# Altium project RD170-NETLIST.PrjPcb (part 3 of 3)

## Sheet 3.SchDoc
size 420 x 297 mm
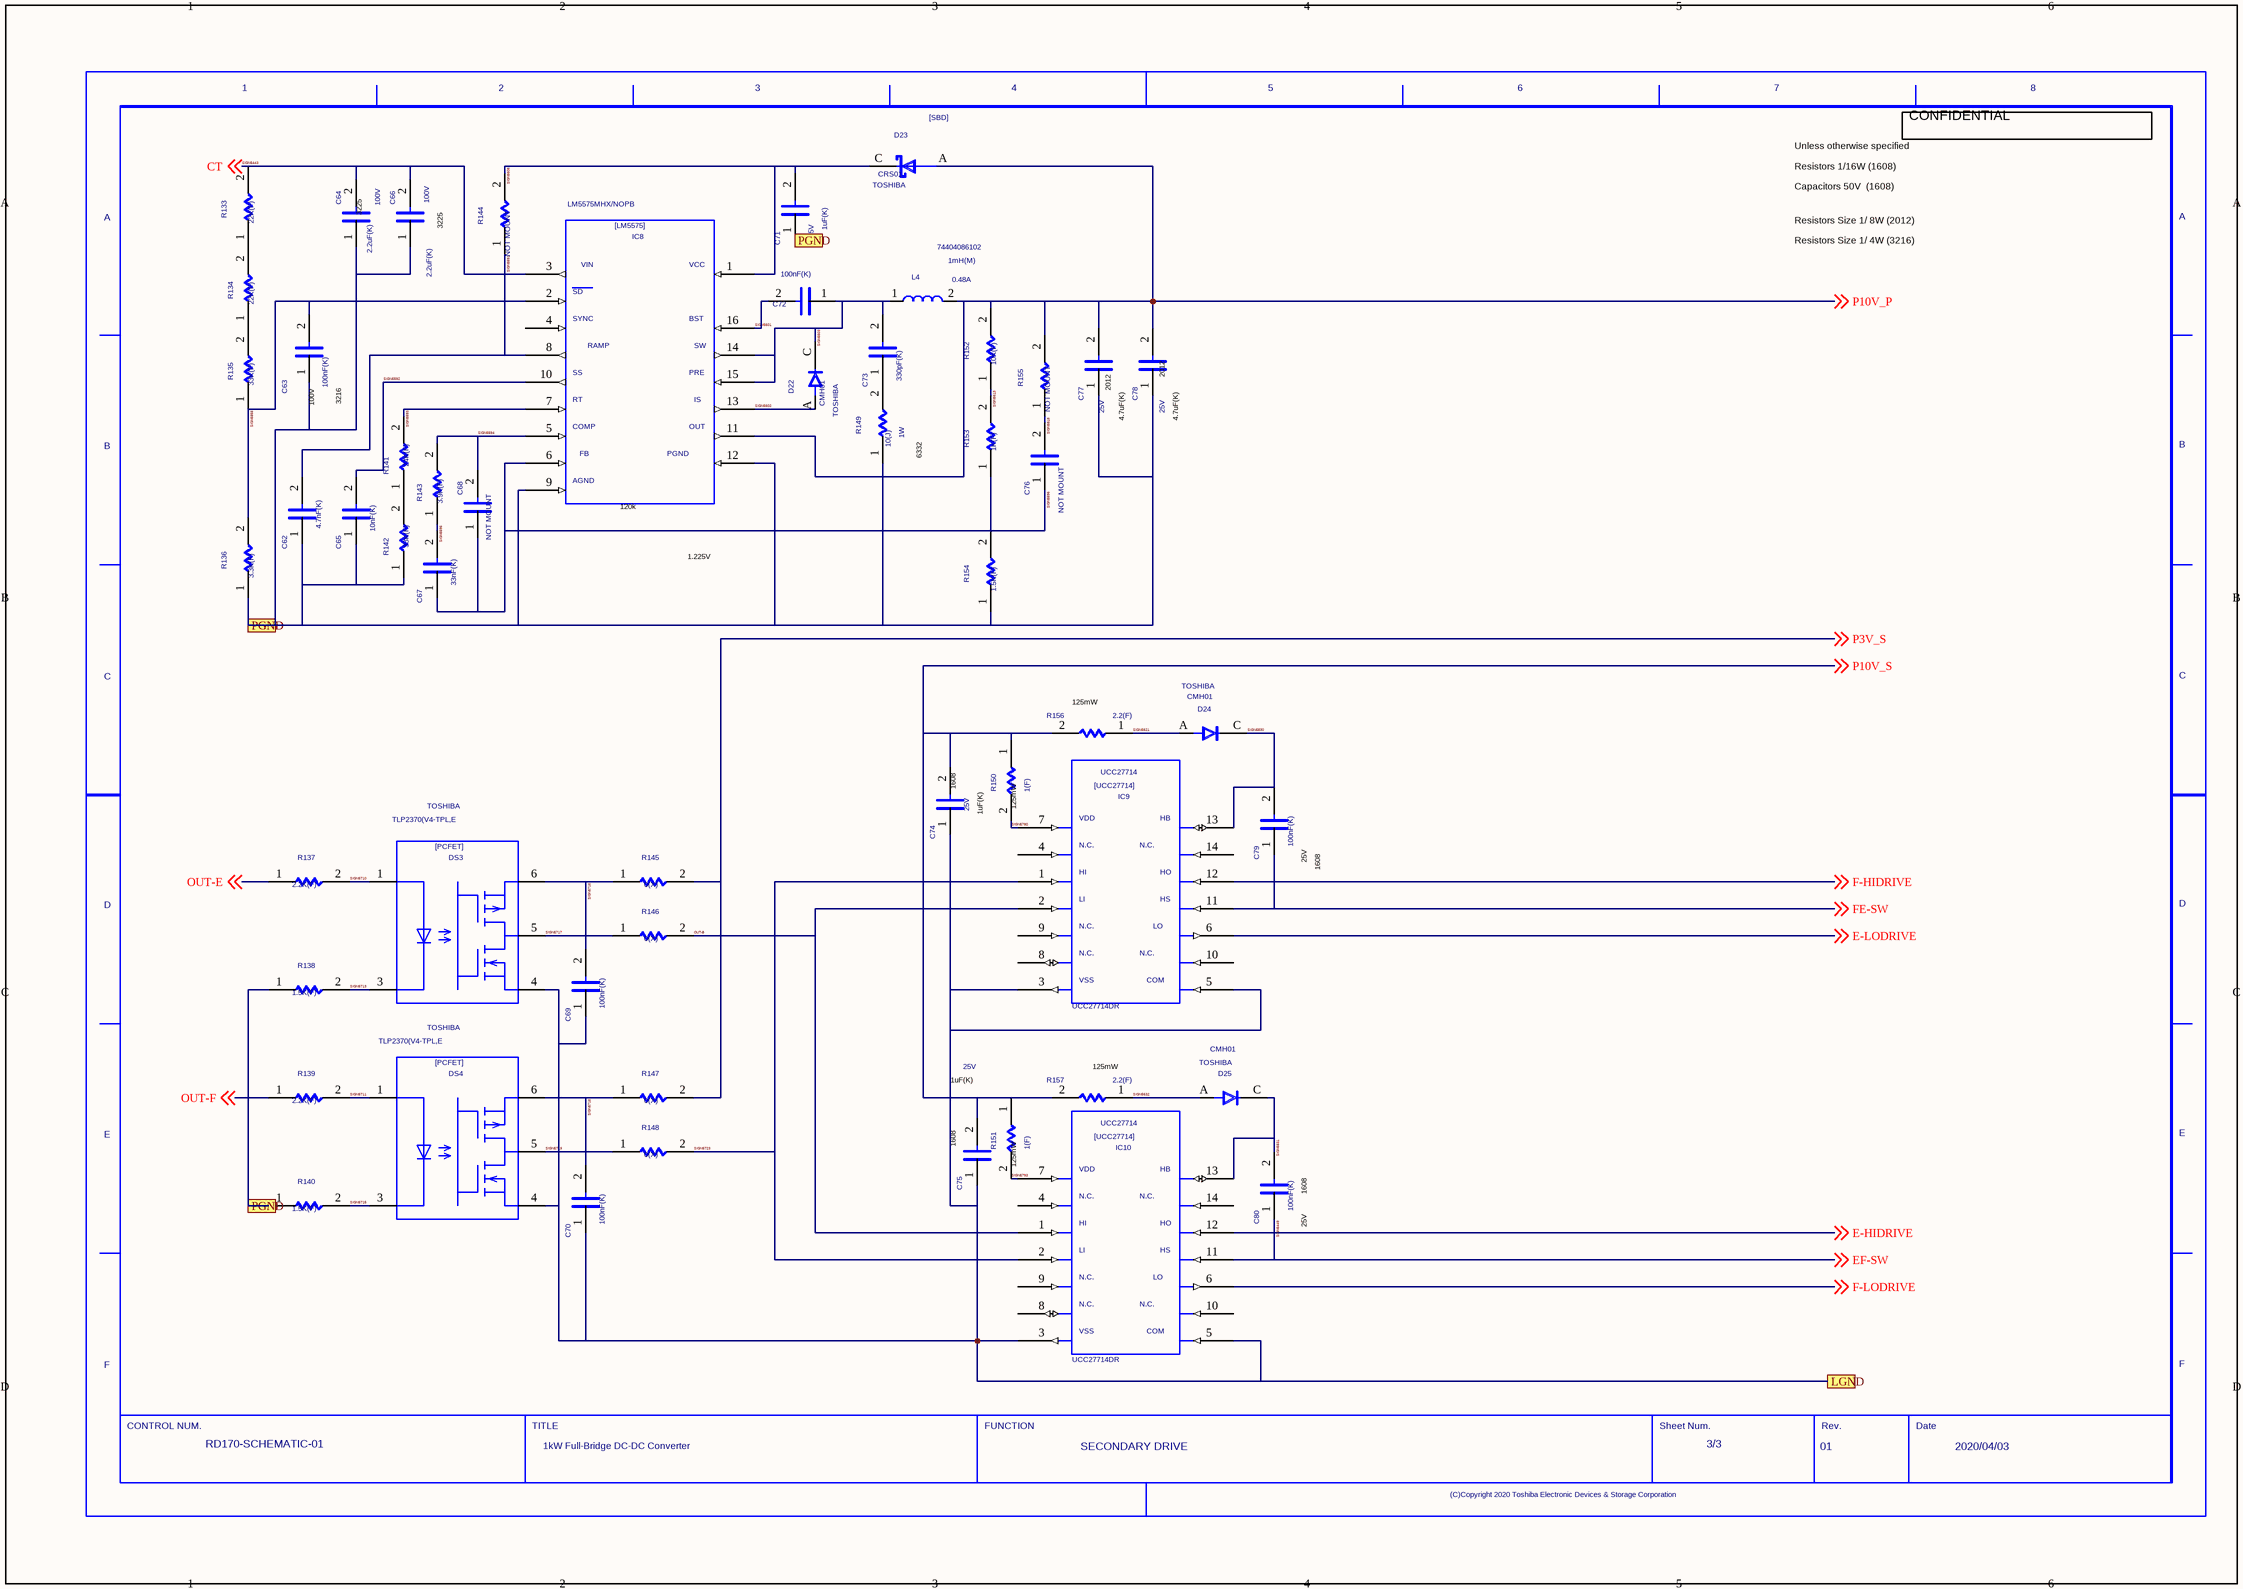
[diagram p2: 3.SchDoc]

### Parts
(Parts that share a designator on the sheet are numbered #1, #2 ... from top to bottom, then left to right.)
C62  VAL1: 4.7nF(K)  (hidden comment: C)
C63  VAL1: 100nF(K)  (hidden comment: C)
C64  VAL2: 100V  VAL1: 2.2uF(K)  (hidden comment: C)
C65  VAL1: 10nF(K)  (hidden comment: C)
C66  VAL2: 100V  VAL1: 2.2uF(K)  (hidden comment: C)
C67  VAL1: 33nF(K)  (hidden comment: C)
C68  NOTMOUNT: NOT MOUNT  (hidden comment: C)
C69  VAL1: 100nF(K)  (hidden comment: C)
C70  VAL1: 100nF(K)  (hidden comment: C)
C71  VAL2: 25V  VAL1: 1uF(K)  (hidden comment: C)
C72  VAL1: 100nF(K)  (hidden comment: C)
C73  VAL1: 330pF(K)  (hidden comment: C)
C74  VAL2: 25V  (hidden comment: C)
C75  VAL2: 25V  (hidden comment: C)
C76  NOTMOUNT: NOT MOUNT  (hidden comment: C)
C77  VAL2: 25V  (hidden comment: C)
C78  VAL2: 25V  (hidden comment: C)
C79  VAL1: 100nF(K)  (hidden comment: C)
C80  VAL1: 100nF(K)  (hidden comment: C)
D22  USERCOMPTEXT3: TOSHIBA  VAL3: CMH01  (hidden comment: D)
D23  USERCOMPTEXT3: TOSHIBA  VAL3: CRS01  (hidden comment: SBD)
D24  USERCOMPTEXT3: TOSHIBA  VAL3: CMH01  (hidden comment: D)
D25  USERCOMPTEXT3: TOSHIBA  VAL3: CMH01  (hidden comment: D)
DS3  USERCOMPTEXT3: TOSHIBA  VAL3: TLP2370(V4-TPL,E  (hidden comment: PCFET)
DS4  USERCOMPTEXT3: TOSHIBA  VAL3: TLP2370(V4-TPL,E  (hidden comment: PCFET)
IC8  VAL3: LM5575MHX/NOPB  (hidden comment: LM5575)
IC9  VAL3: UCC27714DR  (hidden comment: UCC27714)
IC10  VAL3: UCC27714DR  (hidden comment: UCC27714)
L4  VAL3: 74404086102  VAL2: 0.48A  VAL1: 1mH(M)  (hidden comment: L)
R133  VAL1: 22K(F)  (hidden comment: R)
R134  VAL1: 22K(F)  (hidden comment: R)
R135  VAL1: 33K(F)  (hidden comment: R)
R136  VAL1: 3.3K(F)  (hidden comment: R)
R137  VAL1: 2.2K(F)  (hidden comment: R)
R138  VAL1: 1.5K(F)  (hidden comment: R)
R139  VAL1: 2.2K(F)  (hidden comment: R)
R140  VAL1: 1.5K(F)  (hidden comment: R)
R141  VAL1: 24K(F)  (hidden comment: R)
R142  VAL1: 33K(F)  (hidden comment: R)
R143  VAL1: 3.9K(F)  (hidden comment: R)
R144  NOTMOUNT: NOT MOUNT  (hidden comment: R)
R145  VAL1: 0(X)  (hidden comment: R)
R146  VAL1: 0(X)  (hidden comment: R)
R147  VAL1: 0(X)  (hidden comment: R)
R148  VAL1: 0(X)  (hidden comment: R)
R149  VAL2: 1W  VAL1: 10(J)  (hidden comment: R)
R150  VAL1: 1(F)  (hidden comment: R)
R151  VAL1: 1(F)  (hidden comment: R)
R152  VAL1: 10K(F)  (hidden comment: R)
R153  VAL1: 1K(F)  (hidden comment: R)
R154  VAL1: 1.5K(F)  (hidden comment: R)
R155  NOTMOUNT: NOT MOUNT  (hidden comment: R)
R156  VAL1: 2.2(F)  (hidden comment: R)
R157  VAL1: 2.2(F)  (hidden comment: R)
U?#3  DATE: 2020/04/03  TITLE: 1kW Full-Bridge DC-DC Converter  DRAWINGNUMBER: RD170-SCHEMATIC-01  REVISION: 01  SHEETNUMBER: 3/3  FUNCTION: SECONDARY DRIVE  (hidden comment: WAKU_DEF100)

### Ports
LGND, PGND

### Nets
E-HIDRIVE: IC10.12 ; off-sheet E-HIDRIVE
E-LODRIVE: IC9.6 ; off-sheet E-LODRIVE
F-HIDRIVE: IC9.12 ; off-sheet F-HIDRIVE
F-LODRIVE: IC10.6 ; off-sheet F-LODRIVE
FE-SW: C79.1 IC9.11 ; off-sheet FE-SW
OUT-B: IC9.2 IC10.1 R146.2
OUT-E: R137.1 ; off-sheet OUT-E
OUT-F: R139.1 ; off-sheet OUT-F
P3V_S: R145.2 R147.2 ; off-sheet P3V_S
P10V_P: C77.2 C78.2 D23.A IC8.11 L4.2 R152.2 R155.2 ; off-sheet P10V_P
P10V_S: C74.2 C75.2 R150.1 R151.1 R156.2 R157.2 ; off-sheet P10V_S
PGND: C62.1 C63.1 C64.1 C65.1 C66.1 C71.1 C77.1 C78.1 IC8.9 IC8.12 R136.1 R138.1 R140.1 R142.1 R149.1 R154.1 ; port PGND
SIGN5443: C64.2 C66.2 IC8.3 R133.2 ; off-sheet CT  [also labelled CT]
SIGN5449: C80.1 IC10.11 ; off-sheet EF-SW  [also labelled EF-SW]
SIGN5591: C62.2 IC8.8 R144.1
SIGN5592: C65.2 IC8.10
SIGN5593: IC8.7 R141.2
SIGN5594: C68.2 IC8.5 R143.2
SIGN5595: C67.2 R143.1
SIGN5596: C67.1 C68.1 C76.1 IC8.6 R153.1 R154.2
SIGN5601: C72.2 IC8.16
SIGN5602: D22.A IC8.13
SIGN5603: C72.1 C73.2 D22.C IC8.14 IC8.15 L4.1
SIGN5608: C71.2 D23.C IC8.1 R144.2
SIGN5613: R152.1 R153.2
SIGN5621: D24.A R156.1
SIGN5632: D25.A R157.1
SIGN5710: DS3.1 R137.2
SIGN5711: DS4.1 R139.2
SIGN5713: DS3.3 R138.2
SIGN5715: DS4.3 R140.2
SIGN5716: C69.2 DS3.6 R145.1
SIGN5717: DS3.5 R146.1
SIGN5718: C70.2 DS4.6 R147.1
SIGN5719: DS4.5 R148.1
SIGN5723: IC9.1 IC10.2 R148.2
SIGN5780: IC9.7 R150.2
SIGN5793: IC10.7 R151.2
SIGN5818: C76.2 R155.1
SIGN5830: C79.2 D24.C IC9.13
SIGN5831: C80.2 D25.C IC10.13
SIGN5858: C63.2 IC8.2 R135.1 R136.2
SIGN5873: C69.1 C70.1 C74.1 C75.1 DS3.4 DS4.4 IC9.3 IC9.5 IC10.3 IC10.5 ; port LGND
NetC73_1: C73.1 R149.2
NetR133_1: R133.1 R134.2
NetR134_1: R134.1 R135.2
NetR141_1: R141.1 R142.2

Not connected (* = marked no-connect by the designer): IC8 4; IC9 4 8 9 10 14; IC10 4 8 9 10 14

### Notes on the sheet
- CONFIDENTIAL
- Resistors 1/16W (1608)
- Capacitors 50V  (1608)
- Unless otherwise specified
- (near C64) 3225
- (near C66) 3225
- Resistors Size 1/ 8W (2012)
- Resistors Size 1/ 4W (3216)
- (near C77) 2012
- (near C78) 2012
- (near C63) 100V
- (near C63) 3216
- (near R149) 6332
- 4.7uF(K)
- (near C78) 4.7uF(K)
- (near IC8) 120k
- 1.225V
  +-1.47%
- (near R156) 125mW
- (near C74) 1608
- 1uF(K)
- (near R150) 125mW
- (near C79) 25V
- (near C79) 1608
- (near R157) 125mW
- (near C75) 1608
- (near R151) 125mW
- (near C80) 1608
- (near C80) 25V

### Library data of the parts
C62 = C: SQ_PART_MODEL: CON_4.7n; FNPARTSNAMEG: CHIP CERAMIC CAPACITOR (1608); USEINPARTSLIST: YES; PARTNAME: G36030011280; OriginalSymbolOrigin: (2540,7620); ASIMVALUE: 4.7N; MFSOLDERINGPROP: .; TEMPCHARACTERI2: B; MFPACKAGEMETHOP: S; MFFORMINGDIVP: KC; OUMECLASSIFICATION: セラミックコンデンサ; SIZECODESMD: 1608; MFMOUNTSYMBOLP: 80; CDMASTERCADCELG: C8100E; PCODE: P03039090226; FNCLASSCODEG: P03-03; TOLERANCE: K; RATEDVOLTAGE: 50; COMPONENTNAME: G36030011280_package; MAXGCOUNT: 1; OUMEMAKER: MRT 村田製作所; OUMEMAKERKATAMEI: GRM39B472K50PT; VAL2: 50V
C63 = C: SQ_PART_MODEL: CON_100n; FNPARTSNAMEG: CHIP CERAMIC CAPACITOR (3216); USEINPARTSLIST: YES; PARTNAME: G36030031295; OriginalSymbolOrigin: (2540,7620); MFSOLDERINGPROP: .; TEMPCHARACTERI2: B; MFFORMINGDIVP: KC; OUMECLASSIFICATION: セラミックコンデンサ; SIZECODESMD: 3216; ASIMVALUE: 100N; MFMOUNTSYMBOLP: 90; CDMASTERCADCELG: DC901A; PCODE: P03042943816; FNCLASSCODEG: P03-03; MFPACKAGEMETHOP: S; TOLERANCE: K; RATEDVOLTAGE: 50; COMPONENTNAME: G36030031295_package; MAXGCOUNT: 1; OUMEMAKER: TYD 太陽誘電; OUMEMAKERKATAMEI: UMK316BJ104KD-T; VAL2: 100V
C64 C66 = C: SQ_PART_MODEL: CON_1u; FNPARTSNAMEG: CHIP CERAMIC CAPACITOR (3216); USEINPARTSLIST: YES; PARTNAME: G36030013017; OriginalSymbolOrigin: (2540,7620); MFSOLDERINGPROP: .; TEMPCHARACTERI2: B; MFPACKAGEMETHOP: S; MFFORMINGDIVP: KC; OUMECLASSIFICATION: セラミックコンデンサ; SIZECODESMD: 3216; MFMOUNTSYMBOLP: 90; CDMASTERCADCELG: DC901A; PCODE: P03042992821; FNCLASSCODEG: P03-03; TOLERANCE: K; RATEDVOLTAGE: 50; COMPONENTNAME: 5P9L1192P006_package; MAXGCOUNT: 1; OUMEMAKER: 株式会社村田製作所; NOMINALCAPACITA: 1u; OUMEMAKERKATAMEI: GRM31MB31H105KA87L; VAL3: 8.85E+11
C65 = C: SQ_PART_MODEL: CON_10n; FNPARTSNAMEG: CHIP CERAMIC CAPACITOR (1608); USEINPARTSLIST: YES; PARTNAME: G36030011716; OriginalSymbolOrigin: (2540,7620); ASIMVALUE: 10N; MFSOLDERINGPROP: .; TEMPCHARACTERI2: B; MFPACKAGEMETHOP: S; MFFORMINGDIVP: KC; OUMECLASSIFICATION: セラミックコンデンサ; SIZECODESMD: 1608; MFMOUNTSYMBOLP: 80; CDMASTERCADCELG: C8100E; PCODE: P03039A11122; FNCLASSCODEG: P03-03; TOLERANCE: K; RATEDVOLTAGE: 50; COMPONENTNAME: G36030011075_package; MAXGCOUNT: 1; OUMEMAKER: KYC 京セラ; FUNCTION: G36030011075; OUMEMAKERKATAMEI: CM105W5R103K50AT; VAL2: 50V
C67 = C: SQ_PART_MODEL: CON_33n; FNPARTSNAMEG: CHIP CERAMIC CAPACITOR (1608); USEINPARTSLIST: YES; PARTNAME: G36030011310; OriginalSymbolOrigin: (2540,7620); MFSOLDERINGPROP: .; TEMPCHARACTERI2: B; MFPACKAGEMETHOP: S; MFFORMINGDIVP: KC; OUMECLASSIFICATION: セラミックコンデンサ; SIZECODESMD: 1608; MFMOUNTSYMBOLP: 80; CDMASTERCADCELG: C8100E; PCODE: P03039AB8428; FNCLASSCODEG: P03-03; RATEDVOLTAGE: 50; COMPONENTNAME: G510310AM108_package; MAXGCOUNT: 1; OUMEMAKER: ROH ロー・; NOMINALCAPACITA: 33n; OUMEMAKERKATAMEI: MCH185C333KK; VAL2: 50V; CAPACITANCETOLE: K
C68 = C: FNPARTSNAMEG: CHIP CERAMIC CAPACITOR (1608); USEINPARTSLIST: YES; PARTNAME: G36030011488; OriginalSymbolOrigin: (2540,7620); TEMPCHARACTERI2: CH; MFMOUNTSYMBOLP: 80; CDMASTERCADCELG: C8100E; MFSOLDERINGPROP: .; MFPACKAGEMETHOP: S; MFFORMINGDIVP: KC; OUMECLASSIFICATION: セラミックコンデンサ; SIZECODESMD: 1608; PCODE: P03039269127; FNCLASSCODEG: P03-03; RATEDVOLTAGE: 50; COMPONENTNAME: G36030011488_package; MAXGCOUNT: 1; OUMEMAKER: KYC 京セラ; NOMINALCAPACITA: 220p; OUMEMAKERKATAMEI: CM105CH221J50AT; CAPACITANCETOLE: J
C69 C70 = C: SQ_PART_MODEL: CON_100n; FNPARTSNAMEG: CHIP CERAMIC CAPACITOR (1608); PARTCOMMENT: 代表セル<KC0008> がフットプリントに登録されていません。; USEINPARTSLIST: YES; PARTNAME: G36030011839; OriginalSymbolOrigin: (2540,7620); MFSOLDERINGPROP: .; TEMPCHARACTERI2: B; MFFORMINGDIVP: KC; OUMECLASSIFICATION: セラミックコンデンサ; SIZECODESMD: 1608; MFMOUNTSYMBOLP: 80; CDMASTERCADCELG: KC0008; PCODE: P03B000001KW; FNCLASSCODEG: P03-03; MFPACKAGEMETHOP: S; RATEDVOLTAGE: 50; COMPONENTNAME: GDM030001005_package; MAXGCOUNT: 1; OUMEMAKER: MRT 村田製作所; NOMINALCAPACITA: 100n; OUMEMAKERKATAMEI: GRM188B31H104KA92D; VAL2: 50V; CAPACITANCETOLE: K
C71 = C: SQ_PART_MODEL: CON_1u; FNPARTSNAMEG: CHIP CERAMIC CAPACITOR (1608); USEINPARTSLIST: YES; PARTNAME: GDM030000707; PARTCOMMENT: 代表セル<KC0008> がフットプリントに登録されていません。; OriginalSymbolOrigin: (2540,7620); MFSOLDERINGPROP: .; TEMPCHARACTERI2: B; MFPACKAGEMETHOP: S; MFFORMINGDIVP: KC; OUMECLASSIFICATION: セラミックコンデンサ; SIZECODESMD: 1608; MFMOUNTSYMBOLP: 80; CDMASTERCADCELG: KC0008; PCODE: P03B0000016L; FNCLASSCODEG: P03-03; RATEDVOLTAGE: 25; COMPONENTNAME: GDM030000346_package; MAXGCOUNT: 1; OUMEMAKER: KYC 京セラ; NOMINALCAPACITA: 1u; OUMEMAKERKATAMEI: CV105B105K25AT; CAPACITANCETOLE: K
C72 = C: SQ_PART_MODEL: CON_100n; FNPARTSNAMEG: CHIP CERAMIC CAPACITOR (1608); USEINPARTSLIST: YES; PARTNAME: G36030011297; PARTCOMMENT: 代表セル<KC0008> がフットプリントに登録されていません。; OriginalSymbolOrigin: (2540,7620); MAXGCOUNT: 1; COMPONENTNAME: GDM030001005_package; MFSOLDERINGPROP: .; TEMPCHARACTERI2: B; OUMEMAKER: MRT 村田製作所; MFPACKAGEMETHOP: S; MFFORMINGDIVP: KC; OUMECLASSIFICATION: セラミックコンデンサ; MFMOUNTSYMBOLP: 80; OUMEMAKERKATAMEI: GRM188B31H104KA92D; VAL2: 50V; CDMASTERCADCELG: KC0008; PCODE: P03B000001KW; FNCLASSCODEG: P03-03; SIZECODESMD: 1608; RATEDVOLTAGE: 50; NOMINALCAPACITA: 100n; CAPACITANCETOLE: K
C73 = C: SQ_PART_MODEL: CON_330p; FNPARTSNAMEG: CHIP CERAMIC CAPACITOR (1608); USEINPARTSLIST: YES; PARTNAME: GDM030000706; PARTCOMMENT: 代表セル<KC0008> がフットプリントに登録されていません。; OriginalSymbolOrigin: (2540,7620); OUMECLASSIFICATION: セラミックコンデンサ; SIZECODESMD: 1608; CDMASTERCADCELG: KC0008; FNCLASSCODEG: P03-03; RATEDVOLTAGE: 50; COMPONENTNAME: K0300251_package; MAXGCOUNT: 1; OUMEMAKER: ROH; NOMINALCAPACITA: 330p; OUMEMAKERKATAMEI: MCH185CN331KK; VAL2: 50V; CAPACITANCETOLE: K
C74 = C: SQ_PART_MODEL: CON_100n; FNPARTSNAMEG: CHIP CERAMIC CAPACITOR (1608); USEINPARTSLIST: YES; PARTNAME: G36030104036; OriginalSymbolOrigin: (2540,7620); MFSOLDERINGPROP: .; TEMPCHARACTERI2: B; MFPACKAGEMETHOP: S; MFFORMINGDIVP: KC; OUMECLASSIFICATION: セラミックコンデンサ; SIZECODESMD: 1608; MFMOUNTSYMBOLP: 80; CDMASTERCADCELG: C8100E; PCODE: P03039A6F224; FNCLASSCODEG: P03-03; RATEDVOLTAGE: 25; COMPONENTNAME: G36030104036_package; MAXGCOUNT: 1; OUMEMAKER: MRT 村田製作所; NOMINALCAPACITA: 100n; OUMEMAKERKATAMEI: GRM39B104K25PT; VAL1: 1uF(K); CAPACITANCETOLE: K
C75 = C: SQ_PART_MODEL: CON_100n; FNPARTSNAMEG: CHIP CERAMIC CAPACITOR (1608); USEINPARTSLIST: YES; PARTNAME: G36030104036; OriginalSymbolOrigin: (2540,7620); PCODE: P03039A6F224; MFSOLDERINGPROP: .; TEMPCHARACTERI2: B; MFPACKAGEMETHOP: S; MFFORMINGDIVP: KC; OUMECLASSIFICATION: セラミックコンデンサ; SIZECODESMD: 1608; MFMOUNTSYMBOLP: 80; CDMASTERCADCELG: C8100E; FNCLASSCODEG: P03-03; RATEDVOLTAGE: 25; COMPONENTNAME: G36030104036_package; MAXGCOUNT: 1; OUMEMAKER: MRT 村田製作所; NOMINALCAPACITA: 100n; OUMEMAKERKATAMEI: GRM39B104K25PT; VAL1: 1uF(K); CAPACITANCETOLE: K
C76 = C: FNPARTSNAMEG: CHIP CERAMIC CAPACITOR (1608); USEINPARTSLIST: YES; PARTNAME: GDM030000714; PARTCOMMENT: 代表セル<KC0008> がフットプリントに登録されていません。; OriginalSymbolOrigin: (2540,7620); PCODE: P03B000001KW; MFSOLDERINGPROP: .; TEMPCHARACTERI2: B; MFPACKAGEMETHOP: S; MFFORMINGDIVP: KC; OUMECLASSIFICATION: セラミックコンデンサ; SIZECODESMD: 1608; MFMOUNTSYMBOLP: 80; CDMASTERCADCELG: KC0008; FNCLASSCODEG: P03-03; RATEDVOLTAGE: 50; COMPONENTNAME: GDM030001137_package; MAXGCOUNT: 1; OUMEMAKER: MRT 村田製作所; NOMINALCAPACITA: 100n; OUMEMAKERKATAMEI: GRM188B31H104KA92D; CAPACITANCETOLE: K
C77 = C: SQ_PART_MODEL: CON_470n; FNPARTSNAMEG: CHIP CERAMIC CAPACITOR (2012); USEINPARTSLIST: YES; PARTNAME: G36030029759; OriginalSymbolOrigin: (2540,7620); VAL3: 8.85E+11; PCODE: P03261001113; CDMASTERCADCELG: DC910A; MFMOUNTSYMBOLP: 90; MFSOLDERINGPROP: .; TEMPCHARACTERI2: B; MFPACKAGEMETHOP: S; MFFORMINGDIVP: KC; OUMECLASSIFICATION: セラミックコンデンサ; SIZECODESMD: 2012; FNCLASSCODEG: P03-03; RATEDVOLTAGE: 25; COMPONENTNAME: G36030029759_package; MAXGCOUNT: 1; OUMEMAKER: KYC 京セラ; NOMINALCAPACITA: 470n; OUMEMAKERKATAMEI: CM21B474K25AT; VAL1: 4.7uF(K); CAPACITANCETOLE: K
C78 = C: SQ_PART_MODEL: CON_470n; FNPARTSNAMEG: CHIP CERAMIC CAPACITOR (2012); USEINPARTSLIST: YES; PARTNAME: G36030029759; OriginalSymbolOrigin: (2540,7620); VAL3: 8.85E+11; PCODE: P03261001113; MFSOLDERINGPROP: .; TEMPCHARACTERI2: B; MFPACKAGEMETHOP: S; MFFORMINGDIVP: KC; OUMECLASSIFICATION: セラミックコンデンサ; SIZECODESMD: 2012; MFMOUNTSYMBOLP: 90; CDMASTERCADCELG: DC910A; FNCLASSCODEG: P03-03; RATEDVOLTAGE: 25; COMPONENTNAME: G36030029759_package; MAXGCOUNT: 1; OUMEMAKER: KYC 京セラ; NOMINALCAPACITA: 470n; OUMEMAKERKATAMEI: CM21B474K25AT; VAL1: 4.7uF(K); CAPACITANCETOLE: K
C79 = C: SQ_PART_MODEL: CON_100n; FNPARTSNAMEG: CHIP CERAMIC CAPACITOR (3216); USEINPARTSLIST: YES; PARTNAME: G36030104036; OriginalSymbolOrigin: (2540,7620); MFSOLDERINGPROP: .; TEMPCHARACTERI2: B; MFFORMINGDIVP: KC; OUMECLASSIFICATION: セラミックコンデンサ; SIZECODESMD: 3216; ASIMVALUE: 100N; MFMOUNTSYMBOLP: 90; CDMASTERCADCELG: DC901A; PCODE: P03042943816; FNCLASSCODEG: P03-03; MFPACKAGEMETHOP: S; TOLERANCE: K; RATEDVOLTAGE: 50; COMPONENTNAME: G36030031295_package; MAXGCOUNT: 1; OUMEMAKER: TYD 太陽誘電; OUMEMAKERKATAMEI: UMK316BJ104KD-T; VAL2: 25V
C80 = C: SQ_PART_MODEL: CON_100n; FNPARTSNAMEG: CHIP CERAMIC CAPACITOR (3216); USEINPARTSLIST: YES; PARTNAME: G36030104036; OriginalSymbolOrigin: (2540,7620); MFSOLDERINGPROP: .; TEMPCHARACTERI2: B; MFFORMINGDIVP: KC; OUMECLASSIFICATION: セラミックコンデンサ; SIZECODESMD: 3216; ASIMVALUE: 100N; MFMOUNTSYMBOLP: 90; CDMASTERCADCELG: DC901A; PCODE: P03042943816; FNCLASSCODEG: P03-03; MFPACKAGEMETHOP: S; TOLERANCE: K; RATEDVOLTAGE: 50; COMPONENTNAME: G36030031295_package; MAXGCOUNT: 1; OUMEMAKER: TYD 太陽誘電; OUMEMAKERKATAMEI: UMK316BJ104KD-T; VAL2: 50V
D22 D24 D25 = D: USEINPARTSLIST: YES; PARTNAME: 5P9L1110P002; SAVEAREA0: -565,-171,12979,8058; SAVECOUNT: 1; OriginalSymbolOrigin: (2540,5080); COMPONENTNAME: D_D; OUMEMAKER: 東芝; OUMEMAKERKATAMEI: CMF02(TE12R,Q); VAL1: CMH01(TE12L,Q)
D23 = SBD: FNPARTSNAMEG: SCHOTTKY BARRIER DIODE; USEINPARTSLIST: YES; PARTNAME: G36420146011; OUMEPARTTYPE: D; OriginalSymbolOrigin: (0,5080); FORWARDVOLTAGEM: 0; COMPONENTNAME: G36420146011_package; MAXGCOUNT: 1; MAXREPETITIVEPE: 30; MFSOLDERINGPROP: .; OUMEMAKER: TSB 東芝（ＹＰＳＳ）; QUADMODEL: dummymodel; MFPACKAGEMETHOP: S; PEAKFORWARDVOLT: 360m; MFFORMINGDIVP: MM; MOUNTINGFORMSMD: SMD; OUMECLASSIFICATION: 一般整流素子; MFMOUNTSYMBOLP: 80; OUMEMAKERKATAMEI: CRS01(TE85L); VAL1: CRS01(TE85L,Q); CDMASTERCADCELG: DD831R; PCODE: P42471001117; FNCLASSCODEG: P42-03
DS3 DS4 = PCFET: USEINPARTSLIST: YES; PARTNAME: TLP2370_V4-TPL_E; TIME: 11:37:10; UPDATEUSER: q91866sr; UPDATETIME: 16:31:08; SAVECOUNT: 14; SAVEAREA0: -7234,-371,40293,35914; OriginalSymbolOrigin: (5080,33020); MAXGCOUNT: 1; COMPONENTNAME: pinass:PCFET_func:PCFET; OUMEMAKER: 東芝
IC8 = LM5575: USEINPARTSLIST: YES; SAVECOUNT: 74; SAVEAREA0: -22463,-689,65805,66700; TIME: 14:20:25; UPDATEUSER: q91866sr; UPDATETIME: 16:21:18; OriginalSymbolOrigin: (7620,60960); COMPONENTNAME: pinass:LM5575_func:LM5575; MAXGCOUNT: 1; OUMEMAKER: TI
IC9 IC10 = UCC27714: PARTS: 1; SAVECOUNT: 17; SAVEAREA0: -9583,0,50301,45720; TIME: 14:04:55; UPDATEUSER: q91866sr; UPDATETIME: 15:13:25; DEVICENAME: 74HC244AF; DEVICE: 74VHC245; PKG_TYPE: 20PIN; LEVEL: STD; HETERO: 74VHC245,74VHC245_P; OriginalSymbolOrigin: (7620,45720); FUNCTION: IRS21864S
L4 = L: USEINPARTSLIST: YES; OriginalSymbolOrigin: (2540,5080); MAXGCOUNT: 1; COMPONENTNAME: pinass:L_func:L; OUMEMAKER: WURTH
R133 R134 = R: SQ_PART_MODEL: RES_22K; FNPARTSNAMEG: CHIP RESISTOR (1608); USEINPARTSLIST: YES; PARTNAME: G36010011064; OriginalSymbolOrigin: (5080,5080); TOLERANCE: F; ASIMVALUE: 22K; COMPONENTNAME: G36010027089_package; MAXGCOUNT: 1; MFSOLDERINGPROP: .; OUMEMAKER: KOA ＫＯＡ; MFPACKAGEMETHOP: S; MFFORMINGDIVP: KC; MOUNTINGFORMSMD: SMD; OUMECLASSIFICATION: 表面実装用固定抵抗器; MFMOUNTSYMBOLP: 80; POWERRATING: 63m; OUMEMAKERKATAMEI: RK73H1JTD2202F; NUMBEROFELEMENT: 0; VAL2: 63mW; CDMASTERCADCELG: DR802R; PCODE: P01042207426; FNCLASSCODEG: P01-08
R135 = R: SQ_PART_MODEL: RES_33K; FNPARTSNAMEG: CHIP RESISTOR (1608); USEINPARTSLIST: YES; PARTNAME: GDM010001114; OriginalSymbolOrigin: (5080,5080); TOLERANCE: F; ASIMVALUE: 33K; COMPONENTNAME: G36010027171_package; MAXGCOUNT: 1; MFSOLDERINGPROP: .; OUMEMAKER: NAE 松下電子部品; MFPACKAGEMETHOP: S; MFFORMINGDIVP: KC; MOUNTINGFORMSMD: SMD; OUMECLASSIFICATION: 表面実装用固定抵抗器; MFMOUNTSYMBOLP: 80; POWERRATING: 63m; OUMEMAKERKATAMEI: ERJ3GEYF333V; NUMBEROFELEMENT: 0; VAL2: 63mW; CDMASTERCADCELG: DR802R; PCODE: P01042295621; FNCLASSCODEG: P01-08
R136 = R: SQ_PART_MODEL: RES_3.3K; FNPARTSNAMEG: CHIP RESISTOR (1608); USEINPARTSLIST: YES; PARTNAME: GDM010001020; OriginalSymbolOrigin: (5080,5080); TOLERANCE: F; ASIMVALUE: 3.3K; COMPONENTNAME: G36010027027_package; MAXGCOUNT: 1; MFSOLDERINGPROP: .; OUMEMAKER: ROH ロー・; MFPACKAGEMETHOP: S; MFFORMINGDIVP: KC; MOUNTINGFORMSMD: SMD; OUMECLASSIFICATION: 表面実装用固定抵抗器; MFMOUNTSYMBOLP: 80; POWERRATING: 63m; OUMEMAKERKATAMEI: MCR03EZPFX3301; NUMBEROFELEMENT: 0; VAL2: 63mW; CDMASTERCADCELG: DR802R; PCODE: P01042250729; FNCLASSCODEG: P01-08
R137 R139 = R: SQ_PART_MODEL: RES_2.2K; FNPARTSNAMEG: CHIP RESISTOR (1608); USEINPARTSLIST: YES; PARTNAME: G36010104339; OriginalSymbolOrigin: (5080,5080); COMPONENTNAME: G36010104339_package; MAXGCOUNT: 1; MFSOLDERINGPROP: .; OUMEMAKER: KOA ＫＯＡ; MFPACKAGEMETHOP: S; MFFORMINGDIVP: KC; MOUNTINGFORMSMD: SMD; OUMECLASSIFICATION: 表面実装用固定抵抗器; RESISTANCETOLER: F; MFMOUNTSYMBOLP: 80; POWERRATING: 63m; OUMEMAKERKATAMEI: RK73H1JTD2201F; NOMINALRESISTAN: 2.2K; NUMBEROFELEMENT: 0; VAL2: 63mW; CDMASTERCADCELG: DR802R; PCODE: P01042159428; FNCLASSCODEG: P01-08
R138 R140 R154 = R: SQ_PART_MODEL: RES_1.5K; FNPARTSNAMEG: CHIP RESISTOR (1608); USEINPARTSLIST: YES; PARTNAME: G36010027232; OriginalSymbolOrigin: (5080,5080); TOLERANCE: F; COMPONENTNAME: G36010027232_package; MAXGCOUNT: 1; MFSOLDERINGPROP: .; OUMEMAKER: HDK 北陸電気工業; MFPACKAGEMETHOP: S; MFFORMINGDIVP: KC; MOUNTINGFORMSMD: SMD; OUMECLASSIFICATION: 表面実装用固定抵抗器; ASIMVALUE: 1.5K; MFMOUNTSYMBOLP: 80; POWERRATING: 63m; OUMEMAKERKATAMEI: CR1/16 152FV; NUMBEROFELEMENT: 0; VAL2: 63mW; CDMASTERCADCELG: DR802R; PCODE: P01042512223; FNCLASSCODEG: P01-08
R141 = R: SQ_PART_MODEL: RES_24K; FNPARTSNAMEG: CHIP RESISTOR (1608); USEINPARTSLIST: YES; PARTNAME: G36010027A34; OriginalSymbolOrigin: (5080,5080); TOLERANCE: F; COMPONENTNAME: G36010027A34_package; MAXGCOUNT: 1; MFSOLDERINGPROP: .; OUMEMAKER: KOA ＫＯＡ; MFPACKAGEMETHOP: S; MFFORMINGDIVP: KC; MOUNTINGFORMSMD: SMD; OUMECLASSIFICATION: 表面実装用固定抵抗器; ASIMVALUE: 24K; MFMOUNTSYMBOLP: 80; POWERRATING: 63m; OUMEMAKERKATAMEI: RK73H1JTD2402F; NUMBEROFELEMENT: 0; VAL2: 63mW; CDMASTERCADCELG: DR802R; PCODE: P01042223426; FNCLASSCODEG: P01-08
R142 = R: SQ_PART_MODEL: RES_33K; FNPARTSNAMEG: CHIP RESISTOR (1608); USEINPARTSLIST: YES; PARTNAME: G36010027171; OriginalSymbolOrigin: (5080,5080); TOLERANCE: F; COMPONENTNAME: G36010027171_package; MAXGCOUNT: 1; MFSOLDERINGPROP: .; OUMEMAKER: NAE 松下電子部品; MFPACKAGEMETHOP: S; MFFORMINGDIVP: KC; MOUNTINGFORMSMD: SMD; OUMECLASSIFICATION: 表面実装用固定抵抗器; ASIMVALUE: 33K; MFMOUNTSYMBOLP: 80; POWERRATING: 63m; OUMEMAKERKATAMEI: ERJ3GEYF333V; NUMBEROFELEMENT: 0; VAL2: 63mW; CDMASTERCADCELG: DR802R; PCODE: P01042295621; FNCLASSCODEG: P01-08
R143 = R: SQ_PART_MODEL: RES_3.9K; FNPARTSNAMEG: CHIP RESISTOR (1608); USEINPARTSLIST: YES; PARTNAME: G36010027102; OriginalSymbolOrigin: (5080,5080); TOLERANCE: F; COMPONENTNAME: G36010104254_package; MAXGCOUNT: 1; MFSOLDERINGPROP: .; OUMEMAKER: HDK 北陸電気工業; MFPACKAGEMETHOP: S; MFFORMINGDIVP: KC; MOUNTINGFORMSMD: SMD; OUMECLASSIFICATION: 表面実装用固定抵抗器; ASIMVALUE: 3.9K; MFMOUNTSYMBOLP: 80; POWERRATING: 63m; OUMEMAKERKATAMEI: CR1/16 392FV; NUMBEROFELEMENT: 0; VAL2: 63mW; CDMASTERCADCELG: DR802R; PCODE: P01042262227; FNCLASSCODEG: P01-08
R144 = R: FNPARTSNAMEG: CHIP RESISTOR (2012); USEINPARTSLIST: YES; PARTNAME: 5P9L1083P100; OriginalSymbolOrigin: (5080,5080); TOLERANCE: F; COMPONENTNAME: 5P9L1083P100_package; MAXGCOUNT: 1; MFSOLDERINGPROP: .; OUMEMAKER: 北陸電気工業; MFPACKAGEMETHOP: S; MFFORMINGDIVP: KC; MOUNTINGFORMSMD: SMD; OUMECLASSIFICATION: 表面実装用固定抵抗器; MFMOUNTSYMBOLP: 90; POWERRATING: 100m; OUMEMAKERKATAMEI: CR1/10 100FV Pb(F); NOMINALRESISTAN: 10; NUMBEROFELEMENT: 0; CDMASTERCADCELG: DR910A; PCODE: P01043091222; FNCLASSCODEG: P01-08
R145-R148 = R: SQ_PART_MODEL: RES_0; FNPARTSNAMEG: CHIP JUMPER 1608TYPE; USEINPARTSLIST: YES; PARTNAME: G36010014584; PARTCOMMENT: 代表セル<KC0008> がフットプリントに登録されていません。; OriginalSymbolOrigin: (5080,5080); COMPONENTNAME: K0100346_package; MAXGCOUNT: 1; OUMEMAKER: TAT; OUMECLASSIFICATION: 表面実装用固定抵抗器; RESISTANCETOLER: X; POWERRATING: 63m; OUMEMAKERKATAMEI: TSR3GR00V; NOMINALRESISTAN: 0; VAL2: 63mW; CDMASTERCADCELG: KC0008; FNCLASSCODEG: P01-08
R149 = R: SQ_PART_MODEL: RES_10; FNPARTSNAMEG: CHIP RESISTOR (6432); USEINPARTSLIST: YES; PARTNAME: 5P9L1082P003; OriginalSymbolOrigin: (5080,5080); MAXGCOUNT: 1; COMPONENTNAME: 5P9L1082P003_package; MFSOLDERINGPROP: .; OUMEMAKER: 北陸電気工業; MFPACKAGEMETHOP: S; MFFORMINGDIVP: KC; MOUNTINGFORMSMD: SMD; OUMECLASSIFICATION: 表面実装用固定抵抗器; RESISTANCETOLER: J; MFMOUNTSYMBOLP: 80; OUMEMAKERKATAMEI: CR1 100JE Pb(F); NUMBEROFELEMENT: 0; CDMASTERCADCELG: R8100A; PCODE: P01079008317; FNCLASSCODEG: P01-08; NOMINALRESISTAN: 10
R150 R151 = R: SQ_PART_MODEL: RES_1; FNPARTSNAMEG: CHIP RESISTOR (2012); USEINPARTSLIST: YES; PARTNAME: G36010106081; OriginalSymbolOrigin: (5080,5080); COMPONENTNAME: G36010106081_package; MAXGCOUNT: 1; MFSOLDERINGPROP: .; OUMEMAKER: NAE 松下電子部品; MFPACKAGEMETHOP: S; MFFORMINGDIVP: KC; MOUNTINGFORMSMD: SMD; OUMECLASSIFICATION: 表面実装用固定抵抗器; RESISTANCETOLER: F; MFMOUNTSYMBOLP: 90; POWERRATING: 250m; OUMEMAKERKATAMEI: ERJ6RQF1R0V; NUMBEROFELEMENT: 0; VAL2: 125mW; CDMASTERCADCELG: DR910A; PCODE: P01048017210; FNCLASSCODEG: P01-08
R152 = R: SQ_PART_MODEL: RES_10K; FNPARTSNAMEG: CHIP RESISTOR (1608); USEINPARTSLIST: YES; PARTNAME: G36010027034; OriginalSymbolOrigin: (5080,5080); TOLERANCE: F; COMPONENTNAME: G36010027034_package; MAXGCOUNT: 1; MFSOLDERINGPROP: .; OUMEMAKER: SAM 三星電機; MFPACKAGEMETHOP: S; MFFORMINGDIVP: KC; MOUNTINGFORMSMD: SMD; OUMECLASSIFICATION: 表面実装用固定抵抗器; ASIMVALUE: 10K; MFMOUNTSYMBOLP: 80; POWERRATING: 63m; OUMEMAKERKATAMEI: RC1608F103CS; NUMBEROFELEMENT: 0; VAL2: 63mW; CDMASTERCADCELG: DR802R; PCODE: P01042049A26; FNCLASSCODEG: P01-08
R153 = R: SQ_PART_MODEL: RES_1K; FNPARTSNAMEG: CHIP RESISTOR (1608); USEINPARTSLIST: YES; PARTNAME: G36010027027; OriginalSymbolOrigin: (5080,5080); TOLERANCE: F; COMPONENTNAME: G36010027324_package; MAXGCOUNT: 1; MFSOLDERINGPROP: .; OUMEMAKER: HDK 北陸電気工業; MFPACKAGEMETHOP: S; MFFORMINGDIVP: KC; MOUNTINGFORMSMD: SMD; OUMECLASSIFICATION: 表面実装用固定抵抗器; ASIMVALUE: 1K; MFMOUNTSYMBOLP: 80; POWERRATING: 63m; OUMEMAKERKATAMEI: CR1/16 102FV; NUMBEROFELEMENT: 0; VAL2: 63mW; CDMASTERCADCELG: DR802R; PCODE: P01042521225; FNCLASSCODEG: P01-08
R155 = R: FNPARTSNAMEG: CHIP RESISTOR (1608); USEINPARTSLIST: YES; PARTNAME: GDM010001035; PARTCOMMENT: 代表セル<KC0008> がフットプリントに登録されていません。; OriginalSymbolOrigin: (5080,5080); COMPONENTNAME: GDM010001998_package; MAXGCOUNT: 1; MFSOLDERINGPROP: .; OUMEMAKER: TAT 立山科学工業; MFPACKAGEMETHOP: S; MFFORMINGDIVP: KC; MOUNTINGFORMSMD: SMD; OUMECLASSIFICATION: 表面実装用固定抵抗器; RESISTANCETOLER: J; MFMOUNTSYMBOLP: 80; POWERRATING: 100m; OUMEMAKERKATAMEI: TFR3GTJ103V; NOMINALRESISTAN: 10K; NUMBEROFELEMENT: 0; CDMASTERCADCELG: KC0008; PCODE: P01B000002J4; FNCLASSCODEG: P01-08
R156 R157 = R: SQ_PART_MODEL: RES_2.2; FNPARTSNAMEG: CHIP RESISTOR (2012); USEINPARTSLIST: YES; PARTNAME: G36010106012; OriginalSymbolOrigin: (5080,5080); COMPONENTNAME: G36010106012_package; MAXGCOUNT: 1; MFSOLDERINGPROP: .; OUMEMAKER: NAE 松下電子部品; MFPACKAGEMETHOP: S; MFFORMINGDIVP: KC; MOUNTINGFORMSMD: SMD; OUMECLASSIFICATION: 表面実装用固定抵抗器; RESISTANCETOLER: F; MFMOUNTSYMBOLP: 90; POWERRATING: 250m; OUMEMAKERKATAMEI: ERJ6RQF2R2V; NOMINALRESISTAN: 2.2; NUMBEROFELEMENT: 0; VAL2: 125mW; CDMASTERCADCELG: DR910A; PCODE: P01048019214; FNCLASSCODEG: P01-08
U?#3 = WAKU_DEF100: PLOTTIME: HH:MM; SAVEAREA0: 218350,-40131,416688,63935; TIME: 14:30:25; UPDATEUSER: t5459927; UPDATETIME: 13:20:46; SAVECOUNT: 5; OriginalSymbolOrigin: (10160,284480)

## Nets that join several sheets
A-DRIVE: 1 (R1.2 R5.2), 2 (R91.1 R92.1)
AB-SW: 1 (23 pins), 2 (C48.1 IC3.11)
B-DRIVE: 1 (R2.2 R6.2), 2 (R93.1 R94.1)
C-DRIVE: 1 (R10.2 R13.2), 2 (R95.1 R96.1)
CD-SW: 1 (21 pins), 2 (C49.1 IC4.11)
D-DRIVE: 1 (R9.2 R14.2), 2 (R97.1 R98.1)
E-HIDRIVE: 1 (R35.2 R41.2), 3 (IC10.12)
E-LODRIVE: 1 (R27.2 R32.2), 3 (IC9.6)
F-HIDRIVE: 1 (R26.2 R31.2), 3 (IC9.12)
F-LODRIVE: 1 (R36.2 R42.2), 3 (IC10.6)
FE-SW: 1 (27 pins), 3 (C79.1 IC9.11)
OUT-E: 2 (IC5.18), 3 (R137.1)
OUT-F: 2 (IC5.17), 3 (R139.1)
P3V_S: 1 (C43.2 IC2.2 R56.2 R59.2), 3 (R145.2 R147.2)
P10V_P: 2 (7 pins), 3 (7 pins)
P10V_S: 1 (6 pins), 3 (6 pins)
PGND: 1 (45 pins), 2 (35 pins), 3 (16 pins)
SIGN5443: 1 (19 pins), 3 (C64.2 C66.2 IC8.3 R133.2)
SIGN5449: 1 (26 pins), 3 (C80.1 IC10.11)
SIGN5864: 1 (T2.4), 2 (D10.A R60.2)
SIGN5873: 1 (56 pins), 2 (10 pins), 3 (10 pins)
SIGN5875: 1 (19 pins), 2 (8 pins)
